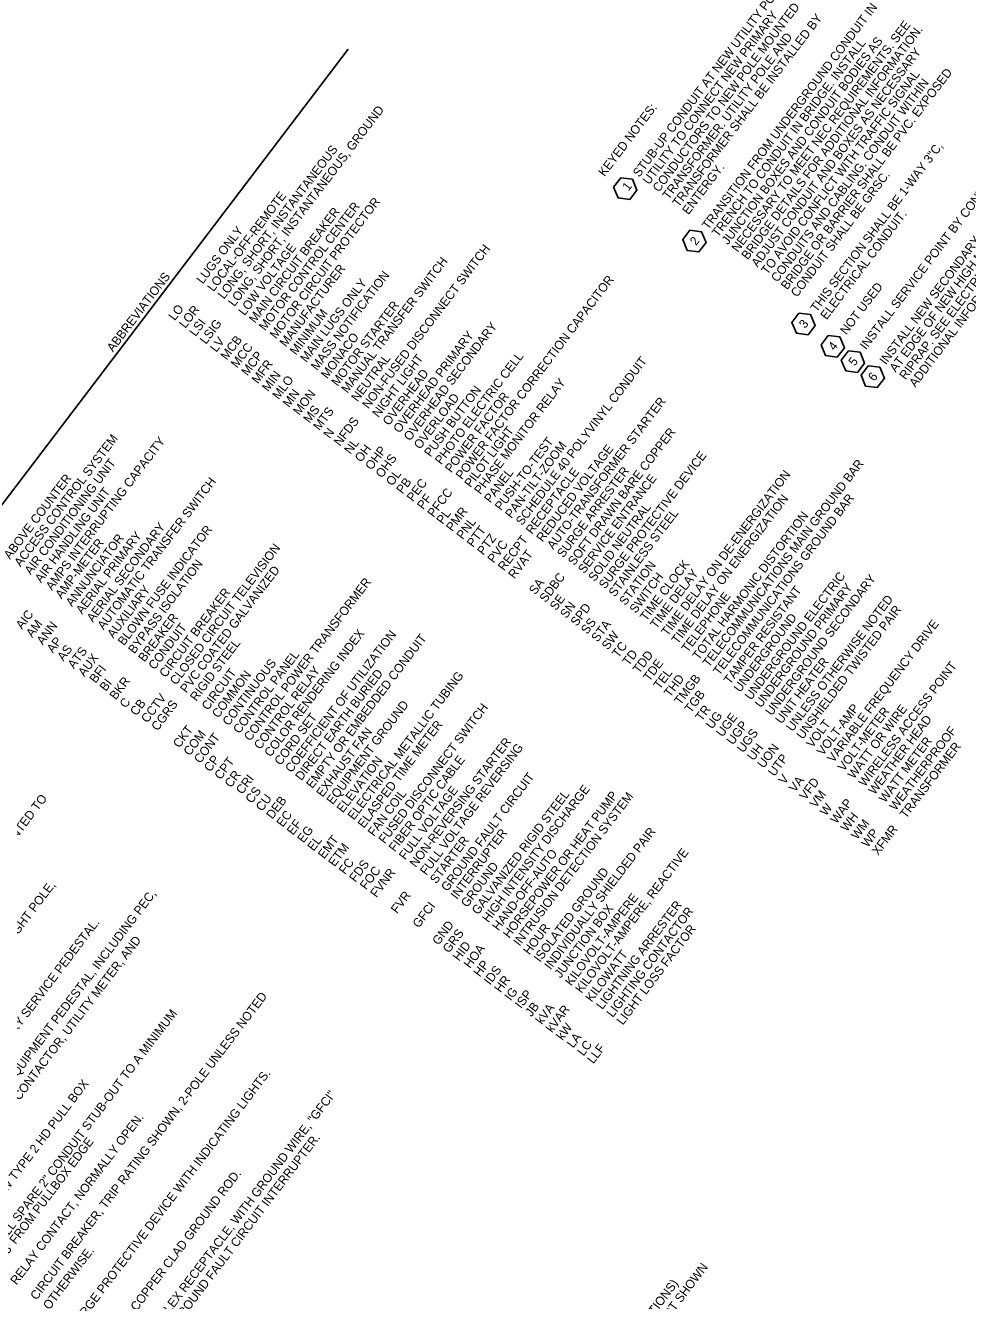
# Model space of a CAD drawing. Extents: x 1289840 to 1300655, y 220865 to 232830.
# Drawn here: x 1298895 to 1299560, y 231149 to 232049 of the extents above; entities that cross this region are included whole.
import ezdxf

# ---------------------------------------------------------------- set-up
doc = ezdxf.new("R2010")
doc.units = 0
for name, color, linetype in [('E-ANNO-KEYN', 7, 'Continuous'), ('E-ANNO-NOTE', 7, 'Continuous'), ('E-ANNO-TEXT', 7, 'Continuous')]:
    doc.layers.add(name, color=color, linetype=linetype)

msp = doc.modelspace()

# ---------------------------------------------------------------- linework, layer by layer
at = {"layer": 'E-ANNO-KEYN'}
for points in [[(1299315.1, 231941.47), (1299323.31, 231940.42), (1299326.51, 231932.79), (1299321.5, 231926.2), (1299313.29, 231927.24), (1299310.09, 231934.88)], [(1299363.88, 231904.37), (1299372.1, 231903.33), (1299375.3, 231895.69), (1299370.29, 231889.1), (1299362.07, 231890.15), (1299358.87, 231897.78)], [(1299440.87, 231845.84), (1299449.08, 231844.8), (1299452.28, 231837.16), (1299447.27, 231830.57), (1299439.06, 231831.62), (1299435.85, 231839.25)], [(1299461.54, 231830.13), (1299469.75, 231829.08), (1299472.95, 231821.45), (1299467.94, 231814.86), (1299459.73, 231815.9), (1299456.53, 231823.54)], [(1299475.79, 231819.29), (1299484, 231818.25), (1299487.2, 231810.61), (1299482.19, 231804.02), (1299473.98, 231805.06), (1299470.77, 231812.7)], [(1299489.76, 231808.66), (1299497.97, 231807.62), (1299501.18, 231799.98), (1299496.16, 231793.39), (1299487.95, 231794.44), (1299484.75, 231802.07)]]:
    msp.add_lwpolyline(points, close=True, dxfattribs=at)
at = {"layer": 'E-ANNO-NOTE'}
msp.add_line((1298835.62, 231654.68), (1299122.78, 232032.31), dxfattribs=at)

# ---------------------------------------------------------------- texts
for s, rotation, p in [('STUB-UP CONDUIT AT NEW UTILITY POLE. ', 52.75013, (1299328.07, 231941.41)), ('TRANSITION FROM UNDERGROUND CONDUIT IN ', 52.75013, (1299376.83, 231904.33)), ('UTILITY TO CONNECT NEW PRIMARY ', 52.75013, (1299335.04, 231936.11)), ('CONDUCTORS TO NEW POLE MOUNTED ', 52.75013, (1299342, 231930.81)), ('TRANSFORMER SHALL BE INSTALLED BY ', 52.75013, (1299355.93, 231920.22)), ('NECESSARY TO MEET NEC REQUIREMENTS. SEE ', 52.75013, (1299397.72, 231888.44)), ('BRIDGE DETAILS FOR ADDITIONAL INFORMATION. ', 52.75013, (1299404.69, 231883.15)), ('TRANSFORMER. UTILITY POLE AND ', 52.75013, (1299348.97, 231925.52)), ('TRENCH TO CONDUIT IN BRIDGE. INSTALL ', 52.75013, (1299383.79, 231899.04)), ('JUNCTION BOXES AND CONDUIT BODIES AS ', 52.75013, (1299390.76, 231893.74)), ('ADJUST CONDUIT AND BOXES AS NECESSARY ', 52.75013, (1299411.65, 231877.85)), ('TO AVOID CONFLICT WITH TRAFFIC SIGNAL ', 52.75013, (1299418.62, 231872.56)), ('CONDUITS AND CABLING. CONDUIT WITHIN ', 52.75013, (1299425.58, 231867.26)), ('BRIDGE OR BARRIER SHALL BE PVC. EXPOSED ', 52.75013, (1299432.55, 231861.96)), ('KEYED NOTES:', 52.75018, (1299303.68, 231941.85)), ('LONG, SHORT, INSTANTANEOUS, GROUND', 52.75013, (1299042.41, 231850.05)), ('INSTALL NEW SECONDARY SERVICE PEDESTAL ', 52.75013, (1299502.2, 231809)), ('LONG, SHORT, INSTANTANEOUS', 52.75013, (1299035.03, 231855.33)), ('THIS SECTION SHALL BE 1-WAY 3"C, ', 52.75013, (1299453.44, 231846.07)), ('INSTALL SERVICE POINT BY CONTRACTOR.', 52.75013, (1299488.27, 231819.59)), ('AT EDGE OF NEW HIGH MAST POLE CONCRETE ', 52.75013, (1299509.16, 231803.7)), ('ENTERGY.', 52.75013, (1299362.9, 231914.93)), ('CONDUIT SHALL BE GRSC.', 52.75013, (1299439.51, 231856.67)), ('LOCAL-OFF-REMOTE', 52.75013, (1299027.64, 231860.59)), ('RIPRAP. SEE ELECTRICAL DETAILS FOR ', 52.75013, (1299516.13, 231798.41)), ('MOTOR CONTROL CENTER', 52.75013, (1299064.17, 231833.02)), ('MOTOR CIRCUIT PROTECTOR', 52.75013, (1299071.78, 231827.33)), ('MAIN CIRCUIT BREAKER', 52.75013, (1299057, 231838.38)), ('ELECTRICAL CONDUIT.', 52.75013, (1299460.41, 231840.78)), ('LUGS ONLY', 52.75013, (1299020.05, 231866.05)), ('LOW VOLTAGE', 52.75013, (1299049.62, 231843.67)), ('NON-FUSED DISCONNECT SWITCH', 52.75013, (1299137.04, 231777.86)), ('MANUAL TRANSFER SWITCH', 52.75013, (1299122.2, 231788.96)), ('MANUFACTURER', 52.75013, (1299078.72, 231821.58)), ('MASS NOTIFICATION', 52.75013, (1299100.8, 231804.94)), ('ADDITIONAL INFORMATION.', 52.75013, (1299523.09, 231793.11)), ('ABBREVIATIONS', 52.75013, (1298956.72, 231818.06)), ('MAIN LUGS ONLY', 52.75013, (1299093.19, 231810.64)), ('POWER FACTOR CORRECTION CAPACITOR', 52.75013, (1299203.04, 231727.97)), ('NOT USED', 52.75013, (1299474.34, 231830.18)), ('LO', 52.75013, (1299000.33, 231840.12)), ('LOR', 52.75013, (1299007.8, 231834.7)), ('MINIMUM', 52.75013, (1299085.9, 231815.84)), ('MOTOR STARTER', 52.75013, (1299115.27, 231793.84)), ('LSI', 52.75013, (1299014.99, 231828.98)), ('LSIG', 52.75013, (1299022.34, 231823.44)), ('OVERHEAD SECONDARY', 52.75013, (1299166.38, 231755.2)), ('MONACO', 52.75013, (1299107.9, 231799.12)), ('OVERHEAD PRIMARY', 52.75013, (1299158.9, 231760.77)), ('LV', 52.75013, (1299029.64, 231817.83)), ('MCB', 52.75013, (1299037, 231812.29)), ('MCC', 52.75013, (1299044.31, 231806.72)), ('MCP', 52.75013, (1299051.64, 231801.15)), ('MFR', 52.75013, (1299058.96, 231795.59)), ('NEUTRAL', 52.75013, (1299129.34, 231782.85)), ('NIGHT LIGHT', 52.75013, (1299144.11, 231771.74)), ('PHOTO ELECTRIC CELL', 52.75013, (1299188.32, 231738.52)), ('SCHEDULE 40 POLYVINYL CONDUIT', 52.75013, (1299245.43, 231695.53)), ('MIN', 52.75013, (1299066.26, 231790.01)), ('OVERHEAD', 52.75013, (1299151.49, 231766.05)), ('MLO', 52.75013, (1299073.61, 231784.44)), ('PUSH BUTTON', 52.75013, (1299180.78, 231743.92)), ('PHASE MONITOR RELAY', 52.75013, (1299216.08, 231717.42)), ('MN', 52.75013, (1299080.92, 231778.84)), ('MON', 52.75013, (1299088.27, 231773.3)), ('OVERLOAD', 52.75013, (1299173.47, 231749.34)), ('POWER FACTOR', 52.75013, (1299195.46, 231732.81)), ('AUTO-TRANSFORMER STARTER', 52.75013, (1299267.47, 231678.61)), ('MS', 52.75013, (1299095.43, 231767.81)), ('MTS', 52.75013, (1299102.39, 231762.56)), ('NFDS', 52.75013, (1299116.99, 231751.49)), ('ACCESS CONTROL SYSTEM', 52.75013, (1298891.4, 231666.41)), ('AMPS INTERRUPTING CAPACITY', 52.75013, (1298913.6, 231649.68)), ('N', 52.75013, (1299109.64, 231756.95)), ('PILOT LIGHT', 52.75013, (1299209.14, 231722.29)), ('PUSH-TO-TEST', 52.75013, (1299230.62, 231706.06)), ('SOFT DRAWN BARE COPPER', 52.75013, (1299282.21, 231667.31)), ('NL', 52.75013, (1299124.29, 231745.85)), ('OH', 52.75013, (1299131.79, 231740.15)), ('OHP', 52.75013, (1299139.13, 231734.62)), ('PAN-TILT-ZOOM', 52.75013, (1299237.91, 231700.54)), ('REDUCED VOLTAGE', 52.75013, (1299259.96, 231683.89)), ('AIR CONDITIONING UNIT', 52.75013, (1298898.65, 231660.75)), ('OHS', 52.75013, (1299146.46, 231729.04)), ('SURGE PROTECTIVE DEVICE', 52.75013, (1299304.02, 231650.7)), ('TELECOMMUNICATIONS MAIN GROUND BAR', 52.75013, (1299377.3, 231595.48)), ('ABOVE COUNTER', 52.75013, (1298883.98, 231671.68)), ('OL', 52.75013, (1299153.79, 231723.46)), ('PANEL', 52.75013, (1299223.12, 231711.45)), ('RECEPTACLE', 52.75013, (1299252.48, 231689.35)), ('SURGE ARRESTER', 52.75013, (1299274.55, 231672.75)), ('SERVICE ENTRANCE', 52.75013, (1299289.36, 231661.56)), ('TIME DELAY ON DE-ENERGIZATION', 52.75013, (1299348.13, 231617.4)), ('AIR HANDLING UNIT', 52.75013, (1298905.92, 231655.09)), ('AUTOMATIC TRANSFER SWITCH', 52.75013, (1298950.04, 231621.96)), ('PB', 52.75013, (1299161.06, 231717.83)), ('PEC', 52.75013, (1299168.43, 231712.34)), ('PF', 52.75013, (1299175.73, 231706.73)), ('PFCC', 52.75013, (1299183.06, 231701.26)), ('TIME DELAY ON ENERGIZATION', 52.75013, (1299355.37, 231611.77)), ('TELECOMMUNICATIONS GROUND BAR', 52.75013, (1299384.68, 231589.67)), ('PL', 52.75013, (1299189.41, 231696.33)), ('PMR', 52.75013, (1299196.2, 231691.26)), ('SOLID NEUTRAL', 52.75013, (1299296.59, 231655.92)), ('STAINLESS STEEL', 52.75013, (1299310.9, 231645.12)), ('TOTAL HARMONIC DISTORTION', 52.75013, (1299370.13, 231600.51)), ('AERIAL SECONDARY', 52.75013, (1298942.56, 231627.24)), ('BLOWN FUSE INDICATOR', 52.75013, (1298964.48, 231610.73)), ('PNL', 52.75013, (1299203.51, 231685.66)), ('PTT', 52.75013, (1299210.83, 231680.1)), ('ANNUNCIATOR', 52.75013, (1298927.75, 231638.28)), ('AERIAL PRIMARY', 52.75013, (1298934.94, 231632.92)), ('PTZ', 52.75013, (1299218.15, 231674.56)), ('RECPT', 52.75013, (1299232.81, 231663.48)), ('AMP-METER', 52.75013, (1298920.34, 231643.84)), ('CLOSED CIRCUIT TELEVISION', 52.75013, (1299001.25, 231582.94)), ('PVC', 52.75013, (1299225.44, 231668.99)), ('RVAT', 52.75013, (1299240.1, 231657.89)), ('BYPASS ISOLATION', 52.75013, (1298971.82, 231604.97)), ('STATION', 52.75013, (1299318.37, 231639.09)), ('TIME CLOCK', 52.75013, (1299333.13, 231628)), ('PVC COATED GALVANIZED', 52.75013, (1299008.53, 231577.31)), ('SDBC', 52.75013, (1299262.12, 231641.14)), ('SWITCH', 52.75013, (1299325.67, 231633.49)), ('TIME DELAY', 52.75013, (1299340.26, 231622.57)), ('UNDERGROUND ELECTRIC', 52.75013, (1299407.07, 231572.23)), ('UNDERGROUND SECONDARY', 52.75013, (1299421.63, 231561.24)), ('AUXILIARY', 52.75013, (1298957, 231615.91)), ('CIRCUIT BREAKER', 52.75013, (1298993.82, 231588.18)), ('CONTROL POWER TRANSFORMER', 52.75013, (1299053.54, 231543.31)), ('SA', 52.75013, (1299254.75, 231646.65)), ('TAMPER RESISTANT', 52.75013, (1299392.21, 231583.36)), ('UNDERGROUND PRIMARY', 52.75013, (1299414.1, 231566.85)), ('SE', 52.75013, (1299269.41, 231635.51)), ('SN', 52.75013, (1299276.72, 231629.94)), ('TELEPHONE', 52.75013, (1299362.37, 231605.74)), ('UNLESS OTHERWISE NOTED', 52.75013, (1299436.34, 231550.07)), ('AIC', 52.75013, (1298892.5, 231622.26)), ('BREAKER', 52.75013, (1298978.96, 231599.17)), ('SPD', 52.75013, (1299284.06, 231624.41)), ('UNDERGROUND', 52.75013, (1299399.31, 231577.75)), ('UNSHIELDED TWISTED PAIR', 52.75013, (1299443.54, 231544.58)), ('AM', 52.75013, (1298899.68, 231616.5)), ('ANN', 52.75013, (1298907.17, 231611.16)), ('CONDUIT', 52.75013, (1298986.11, 231593.71)), ('SS', 52.75013, (1299291.37, 231618.78)), ('STA', 52.75013, (1299298.73, 231613.26)), ('VARIABLE FREQUENCY DRIVE', 52.75013, (1299465.26, 231528.14)), ('AP', 52.75013, (1298914.36, 231605.43)), ('COLOR RENDERING INDEX', 52.75013, (1299067.92, 231532.11)), ('COEFFICIENT OF UTILIZATION', 52.75013, (1299082.64, 231521.06)), ('EMPTY OR EMBEDDED CONDUIT', 52.75013, (1299097.46, 231509.88)), ('SW', 52.75013, (1299306.03, 231607.66)), ('AS', 52.75013, (1298921.72, 231599.87)), ('ATS', 52.75013, (1298929.11, 231594.39)), ('AUX', 52.75013, (1298936.41, 231588.84)), ('RIGID STEEL', 52.75013, (1299015.52, 231571.49)), ('CONTROL PANEL', 52.75013, (1299045.89, 231548.56)), ('TC', 52.75013, (1299313.35, 231602.1)), ('TD', 52.75013, (1299320.68, 231596.52)), ('TDD', 52.75013, (1299328.03, 231591.01)), ('BFI', 52.75013, (1298944.47, 231584.21)), ('CONTINUOUS', 52.75013, (1299038.38, 231554.1)), ('CONTROL RELAY', 52.75013, (1299060.59, 231537.38)), ('TDE', 52.75013, (1299335.34, 231585.41)), ('UNIT HEATER', 52.75013, (1299428.58, 231555.47)), ('WIRELESS ACCESS POINT', 52.75013, (1299487.44, 231511.14)), ('BI', 52.75013, (1298951.66, 231578.47)), ('BKR', 52.75013, (1298958.68, 231572.49)), ('CIRCUIT', 52.75013, (1299023.69, 231565.1)), ('COMMON', 52.75013, (1299030.99, 231559.58)), ('DIRECT EARTH BURIED', 52.75013, (1299089.75, 231515.42)), ('ELECTRICAL METALLIC TUBING', 52.75013, (1299126.72, 231487.6)), ('TEL', 52.75013, (1299342.67, 231579.84)), ('THD', 52.75013, (1299349.98, 231574.28)), ('TMGB', 52.75013, (1299357.31, 231568.76)), ('TGB', 52.75013, (1299364.6, 231563.17)), ('C', 52.75013, (1298965.76, 231566.58)), ('CB', 52.75013, (1298973.19, 231561.2)), ('CCTV', 52.75013, (1298980.93, 231556.16)), ('CGRS', 52.75013, (1298988.18, 231550.54)), ('EQUIPMENT GROUND', 52.75013, (1299111.84, 231498.53)), ('FUSED DISCONNECT SWITCH', 52.75013, (1299148.51, 231470.93)), ('VOLT-AMP', 52.75013, (1299457.88, 231533.07)), ('WATT OR WIRE', 52.75013, (1299479.71, 231516.65)), ('CORD SET', 52.75013, (1299074.99, 231526.2)), ('TR', 52.75013, (1299372.22, 231557.33)), ('UG', 52.75013, (1299379.58, 231551.79)), ('UGE', 52.75013, (1299386.88, 231546.23)), ('VOLT-METER', 52.75013, (1299472.62, 231521.96)), ('WEATHER HEAD', 52.75013, (1299494.32, 231505.55)), ('CKT', 52.75013, (1299003.47, 231538.5)), ('COM', 52.75013, (1299010.85, 231532.99)), ('EXHAUST FAN', 52.75013, (1299104.63, 231503.8)), ('ELASPED TIME METER', 52.75013, (1299133.85, 231481.87)), ('UGP', 52.75013, (1299394.22, 231540.64)), ('UGS', 52.75013, (1299401.53, 231535.08)), ('VOLT', 52.75013, (1299450.43, 231538.55)), ('WEATHERPROOF', 52.75013, (1299509.16, 231494.27)), ('CONT', 52.75013, (1299018.28, 231527.57)), ('NON-REVERSING STARTER', 52.75013, (1299170.46, 231454.17)), ('WATT METER', 52.75013, (1299501.75, 231499.82)), ('TRANSFORMER', 52.75013, (1299516.48, 231488.66)), ('FIBER OPTIC CABLE', 52.75013, (1299155.7, 231465.18)), ('FULL VOLTAGE REVERSING', 52.75013, (1299177.81, 231448.62)), ('UH', 52.75013, (1299408.83, 231529.48)), ('UON', 52.75013, (1299415.93, 231524.14)), ('UTP', 52.75013, (1299423.49, 231518.36)), ('CP', 52.75013, (1299025.29, 231521.58)), ('CPT', 52.75013, (1299032.68, 231516.1)), ('ELEVATION', 52.75013, (1299119, 231492.75)), ('CR', 52.75013, (1299039.91, 231510.46)), ('CRI', 52.75013, (1299047.91, 231505.74)), ('GROUND FAULT CIRCUIT', 52.75013, (1299192.7, 231437.19)), ('V', 52.75013, (1299430.78, 231512.72)), ('VA', 52.75013, (1299438.14, 231507.2)), ('VFD', 52.75013, (1299445.49, 231501.66)), ('CS', 52.75013, (1299054.6, 231499.32)), ('FAN COIL', 52.75013, (1299140.91, 231476.04)), ('FULL VOLTAGE', 52.75013, (1299162.95, 231459.5)), ('GALVANIZED RIGID STEEL', 52.75013, (1299214.37, 231420.76)), ('HIGH INTENSITY DISCHARGE', 52.75013, (1299221.73, 231415.23)), ('HORSEPOWER OR HEAT PUMP', 52.75013, (1299236.38, 231404.18)), ('INTRUSION DETECTION SYSTEM', 52.75013, (1299243.73, 231398.64)), ('VM', 52.75013, (1299452.83, 231496.13)), ('INSTALL NEW LUMINAIRE, MAST ARM, AND LIGHT POLE, MOUNTED TO ', 52.79521, (1298737.07, 231274.72)), ('CU', 52.75013, (1299061.89, 231493.72)), ('DEB', 52.75013, (1299069.24, 231488.23)), ('W', 52.75013, (1299460.09, 231490.47)), ('WAP', 52.75013, (1299467.46, 231484.96)), ('EC', 52.75013, (1299076.53, 231482.61)), ('EF', 52.75013, (1299083.78, 231476.91)), ('WH', 52.75013, (1299474.72, 231479.39)), ('WM', 52.75013, (1299482.06, 231473.81)), ('EG', 52.75013, (1299091.19, 231471.46)), ('INTERRUPTER', 52.75013, (1299199.47, 231431.65)), ('INDIVIDUALLY SHIELDED PAIR', 52.75013, (1299265.58, 231381.95)), ('WP', 52.75013, (1299489.37, 231468.25)), ('XFMR', 52.75013, (1299496.76, 231462.72)), ('EL', 52.75013, (1299098.34, 231465.68)), ('EMT', 52.75013, (1299105.76, 231460.22)), ('ETM', 52.75013, (1299113.08, 231454.68)), ('STARTER', 52.75013, (1299184.82, 231442.64)), ('HAND-OFF-AUTO', 52.75013, (1299228.82, 231409.44)), ('KILOVOLT-AMPERE, REACTIVE', 52.75013, (1299287.42, 231365.34)), ('FC', 52.75013, (1299120.45, 231449.21)), ('FDS', 52.75013, (1299127.84, 231443.7)), ('FOC', 52.75013, (1299135.36, 231438.4)), ('FVNR', 52.75013, (1299142.71, 231432.88)), ('GROUND', 52.75013, (1299206.73, 231425.93)), ('ISOLATED GROUND', 52.75013, (1299258.12, 231387.24)), ('NEW FOUR LUMINAIRE HIGH MAST FIXTURES, LIGHT POLE, ', 52.79521, (1298770.24, 231249.49)), ('INSTALL NEW ELECTRICAL EQUIPMENT PEDESTAL, INCLUDING PEC, ', 52.79521, (1298818.24, 231212.98)), ('FVR', 52.75013, (1299157.21, 231421.59)), ('KILOVOLT-AMPERE', 52.75013, (1299280.15, 231370.48)), ('GFCI', 52.75013, (1299172.54, 231411.41)), ('JUNCTION BOX', 52.75013, (1299272.66, 231376.04)), ('LIGHTNING ARRESTER', 52.75013, (1299302.13, 231353.87)), ('LIGHTING CONTACTOR', 52.75013, (1299309.53, 231348.26)), ('INSTALL NEW NEMA 4X, SECONDARY SERVICE PEDESTAL.', 52.79521, (1298802.69, 231224.81)), ('GND', 52.75013, (1299186.47, 231399.28)), ('GRS', 52.75013, (1299193.82, 231393.72)), ('HOUR', 52.75013, (1299250.65, 231392.44)), ('LIGHT LOSS FACTOR', 52.75013, (1299316.57, 231342.89)), ('SERVICE TYPE LIGHTING CONTACTOR, UTILITY METER, AND ', 52.79521, (1298827.26, 231206.13)), ('HID', 52.75013, (1299200.99, 231387.98)), ('HOA', 52.75013, (1299208.7, 231382.91)), ('KILOWATT', 52.75013, (1299294.64, 231359.16)), ('HP', 52.75013, (1299215.6, 231376.86)), ('IDS', 52.75013, (1299222.88, 231371.19)), ('HR', 52.75013, (1299230.27, 231365.71)), ('CIRCUIT BREAKER, TRIP RATING SHOWN, 2-POLE UNLESS NOTED ', 52.79521, (1298902.75, 231148.75)), ('IG', 52.75013, (1299237.48, 231359.98)), ('ISP', 52.75013, (1299244.84, 231354.46)), ('INSTALL SPARE 2" CONDUIT STUB-OUT TO A MINIMUM ', 52.75013, (1298868.2, 231175.02)), ('JB', 52.75013, (1299252.02, 231348.73)), ('kVA', 52.75013, (1299259.45, 231343.28)), ('kVAR', 52.75013, (1299266.62, 231337.5)), ('kW', 52.75013, (1299274.03, 231332.06)), ('LA', 52.75013, (1299281.48, 231326.67)), ('LC', 52.75013, (1299288.74, 231321.05)), ('LLF', 52.75013, (1299295.77, 231315.59)), ('SURGE PROTECTIVE DEVICE WITH INDICATING LIGHTS.', 52.79521, (1298930.41, 231127.72)), ('INSTALL NEW TYPE 2 HD PULL BOX', 52.75013, (1298852.54, 231186.92)), ('20 AMP DUPLEX RECEPTACLE, WITH GROUND WIRE, "GFCI" ', 52.75013, (1298966.69, 231100.12)), ('RELAY CONTACT, NORMALLY OPEN.', 52.79521, (1298888.63, 231159.48)), ("OF 3' FROM PULLBOX EDGE", 52.75013, (1298874.42, 231170.28)), ('INDICATES GROUND FAULT CIRCUIT INTERRUPTER.', 52.75013, (1298974.39, 231094.27)), ('3/4" x 10\' COPPER CLAD GROUND ROD.', 52.79521, (1298951.31, 231111.82)), ('OTHERWISE.', 52.79521, (1298911.77, 231141.91)), ('REFER TO SPECIFICATIONS IF NOT SHOWN', 52.75013, (1299269.09, 231030.43)), ('CONDUIT TYPE (SEE ABBREVIATIONS) ', 52.75013, (1299261.39, 231036.28))]:
    msp.add_text(s, height=6.25, rotation=rotation, dxfattribs=at).set_placement(p)
at = {"layer": 'E-ANNO-TEXT'}
for s, p in [('1', (1299320.59, 231931.68)), ('2', (1299368.3, 231893.17)), ('3', (1299445.28, 231834.65)), ('4', (1299465.95, 231818.93)), ('5', (1299480.2, 231808.09)), ('6', (1299494.07, 231797.33))]:
    msp.add_text(s, height=6.25, rotation=52.75013, dxfattribs=at).set_placement(p)

doc.saveas('drawing.dxf')
